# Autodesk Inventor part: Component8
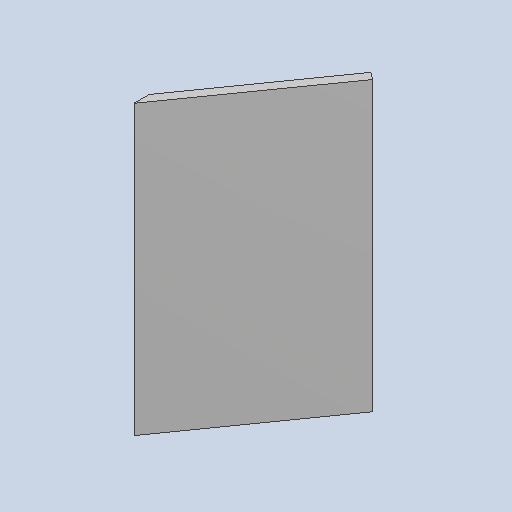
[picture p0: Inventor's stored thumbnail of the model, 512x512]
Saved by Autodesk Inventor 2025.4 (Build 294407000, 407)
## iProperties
Created: 2026-06
Part Number: Component8
Material: Generic
Document SubType Name: Modeling
Designer: AdminForWorker
Density: 1 g/cm^3
Appearance: Default
Title: Component8
Author: AdminForWorker
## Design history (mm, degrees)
feature "Body1"
body "Solid1"
